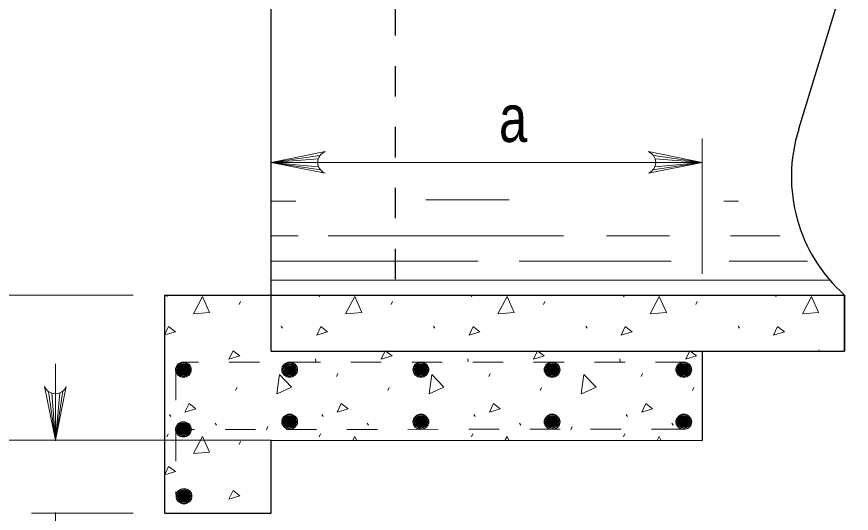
# Model space of a CAD drawing. Extents: x 1083.1 to 1117.1, y 697.4 to 743.4.
# Drawn here: x 1109.836 to 1112.576, y 724.387 to 726.017 of the extents above; entities that cross this region are included whole.
import ezdxf

# ---------------------------------------------------------------- set-up
doc = ezdxf.new("R2010")
doc.units = 0
doc.header["$LTSCALE"] = 0.064
doc.linetypes.add('SHORT_DASHED', pattern=[2.7, 1.5, -1.2])
doc.layers.add('1', color=7, linetype='Continuous', lineweight=13)

msp = doc.modelspace()

# ---------------------------------------------------------------- linework, layer by layer
at = {"layer": '1', "lineweight": 25}
for p, q in [((1110.671, 724.91933), (1110.671, 727.46058)), ((1112.57575, 726.21325), (1112.40292, 725.64783)), ((1110.32192, 724.38733), (1110.322, 725.10275)), ((1110.322, 725.10275), (1112.55383, 725.10283)), ((1110.671, 724.91933), (1112.55375, 724.91933)), ((1112.08658, 724.91933), (1112.08658, 724.62625)), ((1110.671, 724.62633), (1112.08658, 724.62625)), ((1110.671, 724.38733), (1110.671, 724.62633)), ((1110.32192, 724.38733), (1110.671, 724.38733))]:
    msp.add_line(p, q, dxfattribs=at)
at = {"layer": '1', "linetype": 'SHORT_DASHED', "lineweight": 25}
msp.add_line((1111.078, 727.25533), (1111.078, 725.10275), dxfattribs=at)
at = {"layer": '1'}
for p, q in [((1112.08658, 725.1735), (1112.08658, 725.61708)), ((1110.83133, 725.56125), (1110.67108, 725.53883)), ((1110.82592, 725.55017), (1110.67108, 725.53883)), ((1112.08658, 725.53892), (1110.67108, 725.53883)), ((1110.82425, 725.53883), (1110.67108, 725.53883)), ((1110.82708, 725.5245), (1110.67108, 725.53883)), ((1110.83325, 725.51408), (1110.67108, 725.53883)), ((1111.9245, 725.51417), (1112.08658, 725.53892)), ((1111.92633, 725.56142), (1112.08658, 725.53892)), ((1111.93058, 725.52458), (1112.08658, 725.53892)), ((1111.93175, 725.55025), (1112.08658, 725.53892)), ((1111.93342, 725.53892), (1112.08658, 725.53892)), ((1110.67108, 725.41125), (1110.75275, 725.41125)), ((1111.45233, 725.41617), (1111.17875, 725.41617)), ((1112.15683, 725.41133), (1112.20575, 725.41133)), ((1110.67108, 725.29733), (1110.76, 725.29742)), ((1110.858, 725.29733), (1111.63142, 725.29742)), ((1111.77258, 725.29733), (1111.97925, 725.29733)), ((1112.179, 725.29742), (1112.34242, 725.29742)), ((1110.67108, 725.21417), (1111.35083, 725.21425)), ((1111.48508, 725.21417), (1111.98392, 725.21417)), ((1112.17517, 725.21417), (1112.43233, 725.21425)), ((1110.67108, 725.1525), (1112.50475, 725.15258)), ((1108.46833, 725.103), (1110.21792, 725.10275)), ((1110.32908, 725.09725), (1110.3315, 725.10275)), ((1110.82883, 725.09725), (1110.83125, 725.10275)), ((1111.32867, 725.09725), (1111.33108, 725.10275)), ((1111.82842, 725.09725), (1111.83083, 725.10283)), ((1112.32817, 725.09725), (1112.33067, 725.10283)), ((1112.55383, 725.10283), (1112.55375, 724.91933)), ((1110.56592, 725.07183), (1110.57033, 725.08183)), ((1111.06567, 725.07183), (1111.07008, 725.08183)), ((1111.56542, 725.07183), (1111.56983, 725.08183)), ((1112.06517, 725.07183), (1112.06958, 725.08183)), ((1110.70458, 725.00075), (1110.709, 724.99408)), ((1111.20433, 725.00075), (1111.20875, 724.99408)), ((1111.70408, 725.00075), (1111.7085, 724.99408)), ((1112.20392, 725.00075), (1112.20833, 724.99408)), ((1112.46908, 724.92317), (1112.4715, 724.91933)), ((1110.81667, 724.89433), (1110.81783, 724.88442)), ((1111.3165, 724.89433), (1111.31767, 724.88442)), ((1111.81625, 724.89433), (1111.81742, 724.88442)), ((1109.96308, 724.87783), (1109.96308, 724.62425)), ((1110.38617, 724.83542), (1110.39058, 724.84542)), ((1110.88592, 724.83542), (1110.89033, 724.84542)), ((1111.38567, 724.83542), (1111.39008, 724.84542)), ((1111.88542, 724.83542), (1111.88983, 724.84542)), ((1110.55475, 724.79), (1110.55925, 724.8)), ((1111.0545, 724.79), (1111.059, 724.8)), ((1111.55425, 724.79), (1111.55875, 724.8)), ((1112.054, 724.79), (1112.0585, 724.8)), ((1109.94058, 724.78658), (1109.963, 724.62633)), ((1109.95167, 724.78117), (1109.963, 724.62633)), ((1109.98783, 724.78842), (1109.963, 724.62633)), ((1109.97742, 724.78233), (1109.963, 724.62633)), ((1109.963, 724.7795), (1109.963, 724.62633)), ((1110.33742, 724.71125), (1110.34192, 724.70458)), ((1110.83717, 724.71125), (1110.84167, 724.70458)), ((1111.337, 724.71125), (1111.34142, 724.70458)), ((1111.83675, 724.71125), (1111.84125, 724.70458)), ((1110.48692, 724.683), (1110.49133, 724.67633)), ((1110.65575, 724.66125), (1110.66017, 724.67125)), ((1110.98667, 724.683), (1110.99108, 724.67633)), ((1111.15558, 724.66125), (1111.16, 724.67125)), ((1111.4865, 724.683), (1111.49092, 724.67633)), ((1111.65533, 724.66125), (1111.65975, 724.67125)), ((1111.98625, 724.683), (1111.99067, 724.67633)), ((1110.32908, 724.63817), (1110.3335, 724.64817)), ((1110.82883, 724.63817), (1110.83325, 724.64817)), ((1111.32867, 724.63817), (1111.33308, 724.64817)), ((1111.82842, 724.63817), (1111.83283, 724.64817)), ((1110.671, 724.62633), (1109.213, 724.62633)), ((1110.56592, 724.61267), (1110.57033, 724.62267)), ((1109.88442, 724.38733), (1110.21792, 724.38733)), ((1109.96308, 724.38925), (1109.96308, 723.39525))]:
    msp.add_line(p, q, dxfattribs=at)
at = {"layer": '1', "linetype": 'SHORT_DASHED'}
for p, q in [((1112.03292, 724.88325), (1110.38308, 724.88325)), ((1110.35808, 724.85825), (1110.358, 724.44842)), ((1112.02, 724.6625), (1110.38308, 724.66233))]:
    msp.add_line(p, q, dxfattribs=at)
at = {"layer": '1'}
for points in [[(1110.84808, 725.5035), (1110.67108, 725.53883), (1110.84808, 725.57425)], [(1111.90958, 725.50358), (1112.08658, 725.53892), (1111.90958, 725.57433)], [(1110.41608, 725.04183), (1110.44608, 725.09833), (1110.46933, 725.04625), (1110.41725, 725.04183)], [(1110.91583, 725.04183), (1110.94583, 725.09833), (1110.96917, 725.04625), (1110.917, 725.04183)], [(1111.41558, 725.04183), (1111.44558, 725.09833), (1111.46892, 725.04625), (1111.41675, 725.04183)], [(1111.91533, 725.04183), (1111.94533, 725.09833), (1111.96867, 725.04625), (1111.9165, 725.04183)], [(1112.41508, 725.04183), (1112.44508, 725.09833), (1112.46842, 725.04625), (1112.41625, 725.04183)], [(1110.322, 724.97342), (1110.33458, 724.99967), (1110.35683, 724.983), (1110.322, 724.97217)], [(1112.54475, 724.91933), (1112.54525, 724.92042), (1112.54667, 724.91933)], [(1110.68975, 724.77858), (1110.69858, 724.84192), (1110.73833, 724.80083), (1110.69075, 724.77892)], [(1111.1895, 724.77858), (1111.19833, 724.84192), (1111.23808, 724.80083), (1111.1905, 724.77892)], [(1111.68933, 724.77858), (1111.69808, 724.84192), (1111.73783, 724.80083), (1111.69025, 724.77892)], [(1109.99842, 724.80333), (1109.963, 724.62633), (1109.92758, 724.80333)], [(1110.41608, 724.58267), (1110.44608, 724.63925), (1110.46933, 724.58708), (1110.41725, 724.58267)], [(1110.939, 724.62633), (1110.94583, 724.63925), (1110.95158, 724.62633)], [(1111.43875, 724.62625), (1111.44558, 724.63925), (1111.45142, 724.62625)], [(1111.93842, 724.62625), (1111.94533, 724.63925), (1111.95117, 724.62625)], [(1110.32192, 724.51425), (1110.33458, 724.5405), (1110.35683, 724.52383), (1110.32192, 724.513)]]:
    msp.add_lwpolyline(points, dxfattribs=at)
at = {"layer": '1', "lineweight": 25}
msp.add_lwpolyline([(1112.55383, 725.10267), (1112.55383, 724.91925), (1112.55383, 725.10267)], dxfattribs=at)
at = {"layer": '1'}
for points in [[(1110.821, 724.97192), (1110.83433, 724.99967), (1110.85658, 724.983)], [(1111.32083, 724.97192), (1111.33417, 724.99967), (1111.35633, 724.983)], [(1111.82058, 724.97192), (1111.83392, 724.99967), (1111.85617, 724.983)], [(1112.32033, 724.97192), (1112.33367, 724.99967), (1112.35592, 724.983)], [(1110.53283, 724.89267), (1110.54617, 724.92042), (1110.56833, 724.90375)], [(1111.03258, 724.89267), (1111.04592, 724.92042), (1111.06808, 724.90375)], [(1111.53233, 724.89267), (1111.54567, 724.92042), (1111.56783, 724.90375)], [(1112.03217, 724.89267), (1112.0455, 724.92042), (1112.06758, 724.90375)], [(1110.38833, 724.719), (1110.40167, 724.74675), (1110.42392, 724.73008)], [(1110.88808, 724.719), (1110.90142, 724.74675), (1110.92367, 724.73008)], [(1111.38783, 724.719), (1111.40117, 724.74675), (1111.42342, 724.73008)], [(1111.88758, 724.719), (1111.90092, 724.74675), (1111.92317, 724.73008)], [(1110.53283, 724.4335), (1110.54617, 724.46125), (1110.56833, 724.44458)]]:
    msp.add_lwpolyline(points, close=True, dxfattribs=at)
for centre, start, end in [((1110.8624, 725.53891), 112.08782, 247.91395), ((1111.89531, 725.53899), 292.08605, 67.91218), ((1109.96298, 724.8176), 202.08782, 337.91395)]:
    msp.add_arc(centre, 0.0382, start, end, dxfattribs=at)
at = {"layer": '1', "lineweight": 25}
msp.add_ellipse((1112.8992, 725.49174), major_axis=(0.52018, 0), ratio=0.999895, start_param=2.8369312, end_param=3.9862918, dxfattribs=at)
for centre, major_axis in [((1110.38307, 724.85826), (0.02499, 0)), ((1110.38307, 724.85826), (0.02077, 0)), ((1110.73199, 724.85826), (0.02499, 0)), ((1110.73199, 724.85826), (0.02077, 0)), ((1111.16279, 724.85826), (0.02499, 0)), ((1111.16279, 724.85826), (0.02499, 0)), ((1111.16279, 724.85826), (0.02077, 0)), ((1111.59359, 724.85826), (0.02499, 0)), ((1111.59359, 724.85826), (0.02499, 0)), ((1111.59359, 724.85826), (0.02077, 0)), ((1112.02572, 724.85826), (0.02499, 0)), ((1112.02572, 724.85826), (0.02077, 0)), ((1110.38307, 724.85826), (0.01726, 0)), ((1110.38307, 724.85826), (0.01434, 0)), ((1110.38307, 724.85826), (0.01192, 0)), ((1110.38307, 724.85826), (0.0099, 0)), ((1110.38307, 724.85826), (0.00823, 0)), ((1110.38307, 724.85826), (0.00684, 0)), ((1110.38307, 724.85826), (0.00568, 0)), ((1110.38307, 724.85826), (0.00472, 0)), ((1110.38307, 724.85826), (0.00392, 0)), ((1110.38307, 724.85826), (0.00326, 0)), ((1110.38307, 724.85826), (0.00271, 0)), ((1110.38307, 724.85826), (0.00225, 0)), ((1110.38307, 724.85826), (0.00187, 0)), ((1111.16279, 724.85826), (0.01726, 0)), ((1111.16279, 724.85826), (0.01434, 0)), ((1111.16279, 724.85826), (0.01192, 0)), ((1111.16279, 724.85826), (0.0099, 0)), ((1111.16279, 724.85826), (0.00823, 0)), ((1111.16279, 724.85826), (0.00684, 0)), ((1111.16279, 724.85826), (0.00568, 0)), ((1111.16279, 724.85826), (0.00472, 0)), ((1111.16279, 724.85826), (0.00392, 0)), ((1111.16279, 724.85826), (0.00326, 0)), ((1111.16279, 724.85826), (0.00271, 0)), ((1111.16279, 724.85826), (0.00225, 0)), ((1111.16279, 724.85826), (0.00187, 0)), ((1111.59359, 724.85826), (0.01726, 0)), ((1111.59359, 724.85826), (0.01434, 0)), ((1111.59359, 724.85826), (0.01192, 0)), ((1111.59359, 724.85826), (0.0099, 0)), ((1111.59359, 724.85826), (0.00823, 0)), ((1111.59359, 724.85826), (0.00684, 0)), ((1111.59359, 724.85826), (0.00568, 0)), ((1111.59359, 724.85826), (0.00472, 0)), ((1111.59359, 724.85826), (0.00392, 0)), ((1111.59359, 724.85826), (0.00326, 0)), ((1111.59359, 724.85826), (0.00271, 0)), ((1111.59359, 724.85826), (0.00225, 0)), ((1111.59359, 724.85826), (0.00187, 0)), ((1112.02572, 724.85826), (0.01726, 0)), ((1112.02572, 724.85826), (0.01434, 0)), ((1112.02572, 724.85826), (0.01192, 0)), ((1112.02572, 724.85826), (0.0099, 0)), ((1112.02572, 724.85826), (0.00823, 0)), ((1112.02572, 724.85826), (0.00684, 0)), ((1112.02572, 724.85826), (0.00568, 0)), ((1112.02572, 724.85826), (0.00472, 0)), ((1112.02572, 724.85826), (0.00392, 0)), ((1112.02572, 724.85826), (0.00326, 0)), ((1112.02572, 724.85826), (0.00271, 0)), ((1112.02572, 724.85826), (0.00225, 0)), ((1112.02572, 724.85826), (0.00187, 0)), ((1110.38307, 724.66229), (0.02499, 0)), ((1110.73199, 724.68736), (0.02499, 0)), ((1110.73199, 724.68736), (0.02077, 0)), ((1110.73199, 724.68736), (0.01726, 0)), ((1110.73199, 724.68736), (0.01434, 0)), ((1110.73199, 724.68736), (0.01192, 0)), ((1110.73199, 724.68736), (0.0099, 0)), ((1110.73199, 724.68736), (0.00823, 0)), ((1110.73199, 724.68736), (0.00684, 0)), ((1110.73199, 724.68736), (0.00568, 0)), ((1110.73199, 724.68736), (0.00472, 0)), ((1110.73199, 724.68736), (0.00392, 0)), ((1110.73199, 724.68736), (0.00326, 0)), ((1110.73199, 724.68736), (0.00271, 0)), ((1110.73199, 724.68736), (0.00225, 0)), ((1110.73199, 724.68736), (0.00187, 0)), ((1111.16279, 724.68736), (0.02499, 0)), ((1111.16279, 724.68736), (0.02499, 0)), ((1111.16279, 724.68736), (0.02077, 0)), ((1111.16279, 724.68736), (0.01726, 0)), ((1111.16279, 724.68736), (0.01434, 0)), ((1111.16279, 724.68736), (0.01192, 0)), ((1111.16279, 724.68736), (0.0099, 0)), ((1111.16279, 724.68736), (0.00823, 0)), ((1111.16279, 724.68736), (0.00684, 0)), ((1111.16279, 724.68736), (0.00568, 0)), ((1111.16279, 724.68736), (0.00472, 0)), ((1111.16279, 724.68736), (0.00392, 0)), ((1111.16279, 724.68736), (0.00326, 0)), ((1111.16279, 724.68736), (0.00271, 0)), ((1111.16279, 724.68736), (0.00225, 0)), ((1111.16279, 724.68736), (0.00187, 0)), ((1111.59359, 724.68736), (0.02499, 0)), ((1111.59359, 724.68736), (0.02499, 0)), ((1111.59359, 724.68736), (0.02077, 0)), ((1111.59359, 724.68736), (0.01726, 0)), ((1111.59359, 724.68736), (0.01434, 0)), ((1111.59359, 724.68736), (0.01192, 0)), ((1111.59359, 724.68736), (0.0099, 0)), ((1111.59359, 724.68736), (0.00823, 0)), ((1111.59359, 724.68736), (0.00684, 0)), ((1111.59359, 724.68736), (0.00568, 0)), ((1111.59359, 724.68736), (0.00472, 0)), ((1111.59359, 724.68736), (0.00392, 0)), ((1111.59359, 724.68736), (0.00326, 0)), ((1111.59359, 724.68736), (0.00271, 0)), ((1111.59359, 724.68736), (0.00225, 0)), ((1111.59359, 724.68736), (0.00187, 0)), ((1112.02572, 724.68736), (0.02499, 0)), ((1112.02572, 724.68736), (0.02077, 0)), ((1112.02572, 724.68736), (0.01726, 0)), ((1112.02572, 724.68736), (0.01434, 0)), ((1112.02572, 724.68736), (0.01192, 0)), ((1112.02572, 724.68736), (0.0099, 0)), ((1112.02572, 724.68736), (0.00823, 0)), ((1112.02572, 724.68736), (0.00684, 0)), ((1112.02572, 724.68736), (0.00568, 0)), ((1112.02572, 724.68736), (0.00472, 0)), ((1112.02572, 724.68736), (0.00392, 0)), ((1112.02572, 724.68736), (0.00326, 0)), ((1112.02572, 724.68736), (0.00271, 0)), ((1112.02572, 724.68736), (0.00225, 0)), ((1112.02572, 724.68736), (0.00187, 0)), ((1110.38307, 724.66229), (0.02077, 0)), ((1110.38307, 724.66229), (0.01726, 0)), ((1110.38307, 724.66229), (0.01434, 0)), ((1110.38307, 724.66229), (0.01192, 0)), ((1110.38307, 724.66229), (0.0099, 0)), ((1110.38307, 724.66229), (0.00823, 0)), ((1110.38307, 724.66229), (0.00684, 0)), ((1110.38307, 724.66229), (0.00568, 0)), ((1110.38307, 724.66229), (0.00472, 0)), ((1110.38307, 724.66229), (0.00392, 0)), ((1110.38307, 724.66229), (0.00326, 0)), ((1110.38307, 724.66229), (0.00271, 0)), ((1110.38307, 724.66229), (0.00225, 0)), ((1110.38307, 724.66229), (0.00187, 0)), ((1110.38516, 724.44275), (0.02499, 0)), ((1110.38516, 724.44275), (0.02077, 0)), ((1110.38516, 724.44275), (0.01726, 0)), ((1110.38516, 724.44275), (0.01434, 0)), ((1110.38516, 724.44275), (0.01192, 0)), ((1110.38516, 724.44275), (0.0099, 0)), ((1110.38516, 724.44275), (0.00823, 0)), ((1110.38516, 724.44275), (0.00684, 0)), ((1110.38516, 724.44275), (0.00568, 0)), ((1110.38516, 724.44275), (0.00472, 0)), ((1110.38516, 724.44275), (0.00392, 0)), ((1110.38516, 724.44275), (0.00326, 0)), ((1110.38516, 724.44275), (0.00271, 0)), ((1110.38516, 724.44275), (0.00225, 0)), ((1110.38516, 724.44275), (0.00187, 0))]:
    msp.add_ellipse(centre, major_axis=major_axis, ratio=0.999895, dxfattribs=at)
at = {"layer": '1'}
for major_axis in [(0.01726, 0), (0.01434, 0), (0.01192, 0), (0.0099, 0), (0.00823, 0), (0.00684, 0), (0.00568, 0), (0.00472, 0), (0.00392, 0), (0.00326, 0), (0.00271, 0), (0.00225, 0)]:
    msp.add_ellipse((1110.73199, 724.85826), major_axis=major_axis, ratio=0.999895, dxfattribs=at)

# ---------------------------------------------------------------- texts
at = {"layer": '1', "width": 0.8}
msp.add_text('a', height=0.156, dxfattribs=at).set_placement((1111.419, 725.60592))

doc.saveas('drawing.dxf')
